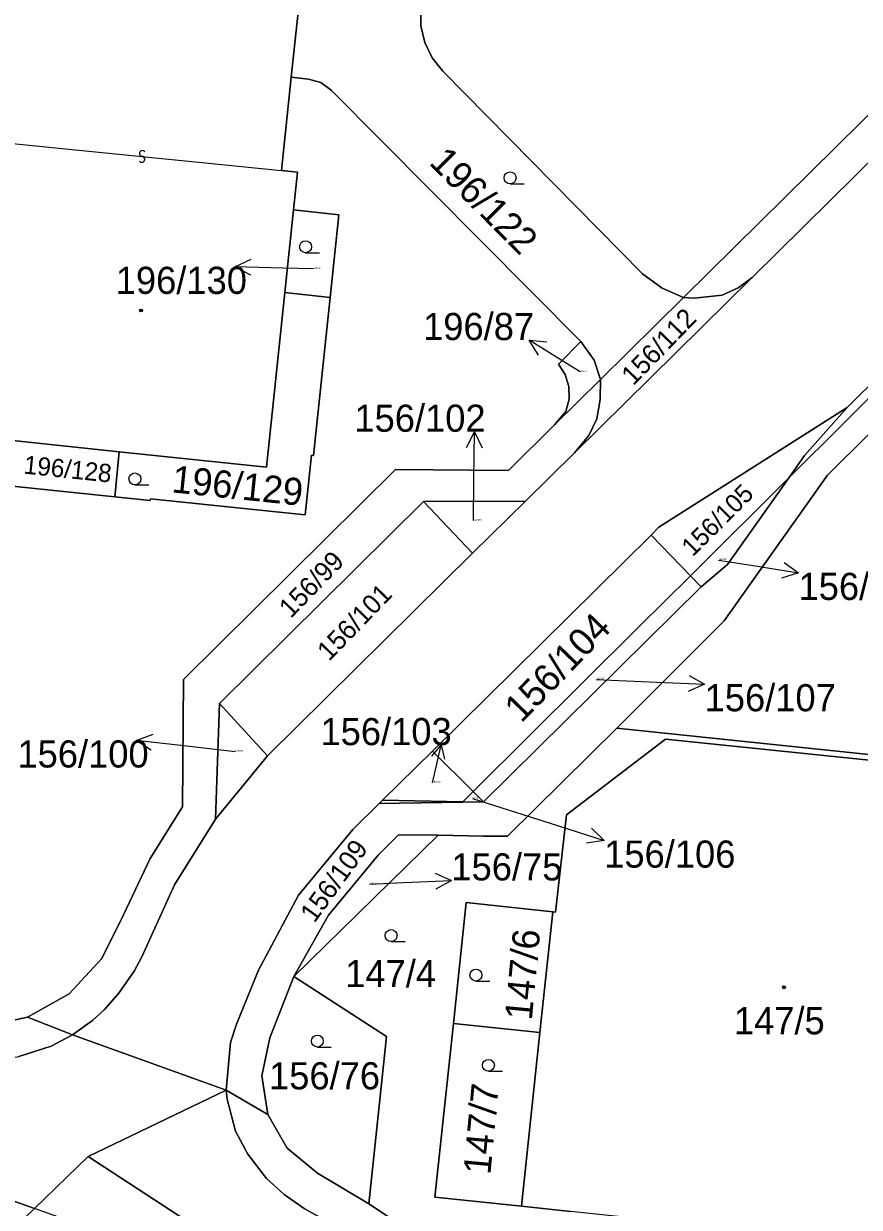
# Model space of a CAD drawing. Extents: x -598233 to -596890, y -1157848 to -1156431.
# Drawn here: x -597801.7 to -597749.4, y -1156820.9 to -1156746.8 of the extents above; entities that cross this region are included whole.
import ezdxf

# ---------------------------------------------------------------- set-up
doc = ezdxf.new("R2010")
doc.units = 0
for name, color, linetype in [('Level 1', 7, 'Continuous'), ('Level 13', 7, 'Continuous'), ('Level 3', 7, 'Continuous'), ('Level 4', 7, 'Continuous'), ('Level 5', 7, 'Continuous'), ('Level 57', 7, 'Continuous'), ('Level 60', 7, 'Continuous')]:
    doc.layers.add(name, color=color, linetype=linetype)

msp = doc.modelspace()

# ---------------------------------------------------------------- linework, layer by layer
at = {"layer": 'Level 1'}
for points in [[(-597750.17, -1156770.82), (-597735.18, -1156755.99), (-597734.6, -1156755.26), (-597730.11, -1156746.9), (-597683.93, -1156701.31), (-597681.14, -1156698.43), (-597679.19, -1156696.78), (-597678.75, -1156696.58)], [(-597760.41, -1156763.93), (-597733.37, -1156737.22), (-597732.06, -1156734.8), (-597732.17, -1156732.25)], [(-597731.89, -1156738.74), (-597756.11, -1156762.68)], [(-597784.23, -1156743.15), (-597784.97, -1156750.15)], [(-597776.66, -1156743.94), (-597776.86, -1156745.86), (-597776.85, -1156746.93), (-597776.61, -1156747.97), (-597776.15, -1156748.94), (-597775.48, -1156749.77), (-597762.97, -1156762.45), (-597761.74, -1156763.35), (-597760.41, -1156763.93)], [(-597784.97, -1156750.15), (-597785.58, -1156755.99)], [(-597766.84, -1156766.68), (-597782.48, -1156750.95), (-597783.13, -1156750.48), (-597783.9, -1156750.26), (-597784.97, -1156750.15)], [(-597731.29, -1156753.36), (-597733.27, -1156757.08), (-597751.4, -1156775.05), (-597757.86, -1156784.17), (-597764.59, -1156790.9)], [(-597753.8, -1156775.21), (-597746.94, -1156768.39), (-597731.29, -1156753.36)], [(-597785.58, -1156755.99), (-597784.59, -1156756.09), (-597784.84, -1156758.45)], [(-597784.84, -1156758.45), (-597785.38, -1156763.63)], [(-597782.54, -1156763.93), (-597782, -1156758.75), (-597784.84, -1156758.45)], [(-597767.23, -1156773.66), (-597756.11, -1156762.68)], [(-597756.11, -1156762.68), (-597756.95, -1156763.31), (-597758, -1156763.78), (-597759.75, -1156763.98), (-597760.41, -1156763.93)], [(-597785.38, -1156763.63), (-597786.52, -1156774.55), (-597795.74, -1156773.59)], [(-597785.38, -1156763.63), (-597782.54, -1156763.93)], [(-597782.54, -1156763.93), (-597783.58, -1156773.83), (-597783.71, -1156773.81), (-597784.1, -1156777.54), (-597793.79, -1156776.53), (-597793.8, -1156776.65), (-597796.03, -1156776.42)], [(-597760.41, -1156763.93), (-597765.61, -1156769.06)], [(-597766.84, -1156766.68), (-597768.25, -1156768.11), (-597767.82, -1156768.76), (-597767.59, -1156769.51), (-597767.57, -1156770.3), (-597767.79, -1156771.07), (-597768.48, -1156771.9)], [(-597766.84, -1156766.68), (-597766.01, -1156767.86), (-597765.61, -1156769.06)], [(-597765.61, -1156769.06), (-597768.48, -1156771.9)], [(-597767.23, -1156773.66), (-597766.35, -1156772.57), (-597765.84, -1156771.54), (-597765.63, -1156770.33), (-597765.61, -1156769.06)], [(-597762.44, -1156778.82), (-597761.95, -1156778.31), (-597750.17, -1156770.82)], [(-597750.17, -1156770.82), (-597752.83, -1156773.83), (-597753.8, -1156775.21)], [(-597768.48, -1156771.9), (-597771.37, -1156774.76), (-597778.44, -1156774.71), (-597791.73, -1156787.84), (-597791.78, -1156795.82), (-597793.81, -1156799.06), (-597795.48, -1156802.59), (-597796.83, -1156805.32), (-597798.87, -1156807.52), (-597801.48, -1156809)], [(-597796.03, -1156776.42), (-597805.27, -1156775.45), (-597804.98, -1156772.62)], [(-597795.74, -1156773.59), (-597804.98, -1156772.62)], [(-597796.03, -1156776.42), (-597795.74, -1156773.59)], [(-597770.31, -1156776.68), (-597767.23, -1156773.66)], [(-597759.98, -1156781.35), (-597753.8, -1156775.21)], [(-597759.3, -1156782.05), (-597757.66, -1156780.66), (-597753.8, -1156775.21)], [(-597789.46, -1156789.36), (-597776.69, -1156776.71)], [(-597776.69, -1156776.71), (-597770.31, -1156776.68)], [(-597776.69, -1156776.71), (-597773.63, -1156779.95)], [(-597770.31, -1156776.68), (-597773.63, -1156779.95)], [(-597776.13, -1156792.33), (-597762.44, -1156778.82)], [(-597759.98, -1156781.35), (-597762.44, -1156778.82)], [(-597773.63, -1156779.95), (-597786.47, -1156792.63)], [(-597773.59, -1156794.86), (-597763.24, -1156784.58), (-597759.98, -1156781.35)], [(-597759.3, -1156782.05), (-597759.98, -1156781.35)], [(-597759.3, -1156782.05), (-597772.94, -1156795.51)], [(-597789.46, -1156789.36), (-597789.71, -1156796.6)], [(-597786.47, -1156792.63), (-597789.46, -1156789.36)], [(-597775.77, -1156797.6), (-597772.94, -1156797.65), (-597771.43, -1156797.65), (-597764.59, -1156790.9)], [(-597764.59, -1156790.9), (-597745.4, -1156792.91)], [(-597768.59, -1156802.39), (-597768.42, -1156802.41), (-597767.74, -1156796.33), (-597761.55, -1156791.58), (-597737.44, -1156794.07), (-597740.62, -1156823.77), (-597742.4, -1156823.59)], [(-597789.71, -1156796.6), (-597786.47, -1156792.63)], [(-597779.26, -1156795.41), (-597776.13, -1156792.33)], [(-597776.13, -1156792.33), (-597773.59, -1156794.86)], [(-597773.59, -1156794.86), (-597774.24, -1156795.5), (-597779.26, -1156795.41)], [(-597773.59, -1156794.86), (-597772.94, -1156795.51)], [(-597779.47, -1156795.62), (-597781.12, -1156797.24), (-597784.51, -1156801.35), (-597787.02, -1156806.05), (-597788.4, -1156809.43), (-597788.78, -1156810.58), (-597789.04, -1156813.57)], [(-597779.47, -1156795.62), (-597779.26, -1156795.41)], [(-597772.94, -1156795.51), (-597779.47, -1156795.62)], [(-597798.68, -1156810.1), (-597797.42, -1156809.19), (-597796.67, -1156808.5), (-597795.77, -1156807.49), (-597794.82, -1156806.12), (-597794.33, -1156805.21), (-597792.28, -1156800.71), (-597789.71, -1156796.6)], [(-597775.77, -1156797.6), (-597778.26, -1156797.58), (-597779.54, -1156798.84), (-597782.64, -1156802.6), (-597784.82, -1156806.44)], [(-597775.77, -1156797.6), (-597784.82, -1156806.44)], [(-597768.59, -1156802.39), (-597774.02, -1156801.82), (-597774.82, -1156809.38)], [(-597769.4, -1156809.95), (-597768.59, -1156802.39)], [(-597801.48, -1156809), (-597804.42, -1156809.62), (-597807.4, -1156809.34), (-597812.36, -1156808.22), (-597817.37, -1156807.35), (-597822.41, -1156806.73), (-597827.48, -1156806.37), (-597836.01, -1156805.98), (-597837.54, -1156805.91), (-597839.05, -1156805.84), (-597839.64, -1156805.81)], [(-597784.82, -1156806.44), (-597786.32, -1156810.29), (-597786.82, -1156812.67), (-597786.44, -1156815.08)], [(-597784.82, -1156806.44), (-597779.01, -1156810.19), (-597780.11, -1156820.68)], [(-597836.2, -1156808.1), (-597829.16, -1156808.42), (-597825.15, -1156808.67), (-597817.18, -1156809.57), (-597812.21, -1156810.42), (-597807.35, -1156811.52), (-597806.36, -1156811.78), (-597805.14, -1156811.86), (-597803.99, -1156811.81), (-597802.03, -1156811.45), (-597800.01, -1156810.81), (-597798.68, -1156810.1)], [(-597798.68, -1156810.1), (-597801.48, -1156809)], [(-597774.82, -1156809.38), (-597775.98, -1156820.26), (-597770.56, -1156820.83)], [(-597774.82, -1156809.38), (-597769.4, -1156809.95)], [(-597789.04, -1156813.57), (-597798.68, -1156810.1)], [(-597769.4, -1156809.95), (-597770.56, -1156820.83)], [(-597789.04, -1156813.57), (-597797.68, -1156817.71)], [(-597758.96, -1156837.3), (-597779, -1156824.02), (-597781.84, -1156822.26), (-597784.16, -1156820.96), (-597785.42, -1156820.1), (-597786.53, -1156819.08), (-597787.7, -1156817.57), (-597788.47, -1156816.13), (-597788.99, -1156814.13), (-597789.04, -1156813.57)], [(-597786.44, -1156815.08), (-597789.04, -1156813.57)], [(-597786.44, -1156815.08), (-597785.23, -1156817.2), (-597783.34, -1156818.75), (-597780.11, -1156820.68)], [(-597801.05, -1156820.96), (-597805.48, -1156819.41), (-597808.5, -1156818.55), (-597813.36, -1156817.31)], [(-597797.68, -1156817.71), (-597801.05, -1156820.96)], [(-597797.68, -1156817.71), (-597707.2, -1156876.79)], [(-597756.23, -1156836.53), (-597780.11, -1156820.68)], [(-597770.56, -1156820.83), (-597767.49, -1156821.15)]]:
    msp.add_lwpolyline(points, dxfattribs=at)
at = {"layer": 'Level 13'}
for centre, start, end in [((-597794.29, -1156754.917), 31.58746, 263.68546), ((-597794.329, -1156755.283), 211.37301, 83.96301)]:
    msp.add_arc(centre, 0.184, start, end, dxfattribs=at)
at = {"layer": 'Level 3'}
msp.add_lwpolyline([(-597803.05, -1156754.22), (-597785.58, -1156755.99)], dxfattribs=at)
at = {"layer": 'Level 5'}
for p, q in [((-597771.27, -1156756.82), (-597770.395, -1156756.82)), ((-597784.08, -1156761.13), (-597783.205, -1156761.13)), ((-597794.76, -1156775.67), (-597793.885, -1156775.67)), ((-597778.72, -1156804.26), (-597777.845, -1156804.26)), ((-597773.41, -1156806.73), (-597772.535, -1156806.73)), ((-597783.34, -1156810.86), (-597782.465, -1156810.86)), ((-597772.63, -1156812.38), (-597771.755, -1156812.38))]:
    msp.add_line(p, q, dxfattribs=at)
for centre, radius in [((-597771.27, -1156756.445), 0.375), ((-597784.08, -1156760.755), 0.375), ((-597794.38, -1156764.75), 0.09), ((-597794.38, -1156764.75), 0.0521), ((-597794.76, -1156775.295), 0.375), ((-597778.72, -1156803.885), 0.375), ((-597773.41, -1156806.355), 0.375), ((-597754.12, -1156807.12), 0.09), ((-597754.12, -1156807.12), 0.0521), ((-597783.34, -1156810.485), 0.375), ((-597772.63, -1156812.005), 0.375)]:
    msp.add_circle(centre, radius, dxfattribs=at)
at = {"layer": 'Level 57'}
for p, q in [((-597785.501, -1156762.089), (-597788.5, -1156762.01)), ((-597783.59, -1156762.14), (-597785.501, -1156762.089)), ((-597767.536, -1156768.187), (-597770.082, -1156766.6)), ((-597766.89, -1156768.59), (-597767.536, -1156768.187)), ((-597773.532, -1156775.34), (-597773.499, -1156772.34)), ((-597773.56, -1156777.9), (-597773.532, -1156775.34)), ((-597758.22, -1156780.37), (-597756.172, -1156780.697)), ((-597756.172, -1156780.697), (-597753.21, -1156781.17)), ((-597765.89, -1156787.84), (-597762.087, -1156788.008)), ((-597762.087, -1156788.008), (-597759.09, -1156788.14)), ((-597791.699, -1156792.001), (-597794.68, -1156791.66)), ((-597788.48, -1156792.37), (-597791.699, -1156792.001)), ((-597776.12, -1156794.31), (-597775.597, -1156791.96)), ((-597773.62, -1156795.3), (-597768.238, -1156797.018)), ((-597768.238, -1156797.018), (-597765.38, -1156797.93)), ((-597780.08, -1156800.66), (-597777.945, -1156800.564)), ((-597777.945, -1156800.564), (-597774.948, -1156800.43))]:
    msp.add_line(p, q, dxfattribs=at)
for points in [[(-597787.514, -1156762.536), (-597788.5, -1156762.01), (-597787.487, -1156761.536)], [(-597769.498, -1156767.553), (-597770.082, -1156766.6), (-597768.969, -1156766.705)], [(-597774.01, -1156773.335), (-597773.499, -1156772.34), (-597773.01, -1156773.346)], [(-597754.118, -1156780.519), (-597753.21, -1156781.17), (-597754.276, -1156781.506)], [(-597760.067, -1156787.597), (-597759.09, -1156788.14), (-597760.111, -1156788.596)], [(-597793.743, -1156792.27), (-597794.68, -1156791.66), (-597793.629, -1156791.277)], [(-597776.163, -1156792.656), (-597775.597, -1156791.96), (-597775.379, -1156792.831)], [(-597766.181, -1156797.15), (-597765.38, -1156797.93), (-597766.485, -1156798.102)], [(-597775.969, -1156799.975), (-597774.948, -1156800.43), (-597775.925, -1156800.974)]]:
    msp.add_lwpolyline(points, dxfattribs=at)
at = {"layer": 'Level 60'}
for points in [[(-597752.83, -1156773.83), (-597750.17, -1156770.82), (-597735.18, -1156755.99), (-597734.6, -1156755.26), (-597730.11, -1156746.9), (-597683.93, -1156701.31), (-597681.14, -1156698.43), (-597679.19, -1156696.78), (-597678.75, -1156696.58), (-597675.04, -1156699.81), (-597675.83, -1156699.36), (-597676.94, -1156699.05), (-597678.16, -1156699.1), (-597679.43, -1156699.58), (-597680.62, -1156700.99), (-597705.61, -1156725.68), (-597717.97, -1156737.89), (-597718.07, -1156737.79), (-597728.48, -1156748.08), (-597731.29, -1156753.36), (-597746.94, -1156768.39), (-597753.8, -1156775.21)], [(-597756.11, -1156762.68), (-597756.95, -1156763.31), (-597758, -1156763.78), (-597759.75, -1156763.98), (-597760.41, -1156763.93), (-597733.37, -1156737.22), (-597732.06, -1156734.8), (-597732.17, -1156732.25), (-597730.57, -1156730.67), (-597729.92, -1156732.43), (-597729.82, -1156733.16), (-597730.03, -1156735.4), (-597730.68, -1156737.11), (-597731.89, -1156738.74)], [(-597785.58, -1156755.99), (-597784.59, -1156756.09), (-597784.84, -1156758.45), (-597785.38, -1156763.63), (-597786.52, -1156774.55), (-597795.74, -1156773.59), (-597804.98, -1156772.62), (-597803.83, -1156761.7), (-597803.05, -1156754.22), (-597805.88, -1156753.92), (-597811.48, -1156753.34), (-597815.37, -1156752.93), (-597824.55, -1156751.97), (-597833.78, -1156751.01), (-597832.65, -1156740.21), (-597832.09, -1156734.89), (-597831.85, -1156732.55), (-597813.46, -1156734.47), (-597783.65, -1156737.59), (-597784.23, -1156743.15), (-597784.97, -1156750.15)], [(-597776.66, -1156743.94), (-597776.86, -1156745.86), (-597776.85, -1156746.93), (-597776.61, -1156747.97), (-597776.15, -1156748.94), (-597775.48, -1156749.77), (-597762.97, -1156762.45), (-597761.74, -1156763.35), (-597760.41, -1156763.93), (-597765.61, -1156769.06), (-597766.01, -1156767.86), (-597766.84, -1156766.68), (-597782.48, -1156750.95), (-597783.13, -1156750.48), (-597783.9, -1156750.26), (-597784.97, -1156750.15), (-597784.23, -1156743.15)], [(-597782, -1156758.75), (-597782.54, -1156763.93), (-597785.38, -1156763.63), (-597784.84, -1156758.45)], [(-597767.23, -1156773.66), (-597766.35, -1156772.57), (-597765.84, -1156771.54), (-597765.63, -1156770.33), (-597765.61, -1156769.06), (-597760.41, -1156763.93), (-597759.75, -1156763.98), (-597758, -1156763.78), (-597756.95, -1156763.31), (-597756.11, -1156762.68)], [(-597782.54, -1156763.93), (-597783.58, -1156773.83), (-597783.71, -1156773.81), (-597784.1, -1156777.54), (-597793.79, -1156776.53), (-597793.8, -1156776.65), (-597796.03, -1156776.42), (-597795.74, -1156773.59), (-597786.52, -1156774.55), (-597785.38, -1156763.63)], [(-597768.25, -1156768.11), (-597766.84, -1156766.68), (-597766.01, -1156767.86), (-597765.61, -1156769.06), (-597768.48, -1156771.9), (-597767.79, -1156771.07), (-597767.57, -1156770.3), (-597767.59, -1156769.51), (-597767.82, -1156768.76)], [(-597798.68, -1156810.1), (-597801.48, -1156809), (-597798.87, -1156807.52), (-597796.83, -1156805.32), (-597795.48, -1156802.59), (-597793.81, -1156799.06), (-597791.78, -1156795.82), (-597791.73, -1156787.84), (-597778.44, -1156774.71), (-597771.37, -1156774.76), (-597768.48, -1156771.9), (-597765.61, -1156769.06), (-597765.63, -1156770.33), (-597765.84, -1156771.54), (-597766.35, -1156772.57), (-597767.23, -1156773.66), (-597770.31, -1156776.68), (-597776.69, -1156776.71), (-597789.46, -1156789.36), (-597789.71, -1156796.6), (-597792.28, -1156800.71), (-597794.33, -1156805.21), (-597794.82, -1156806.12), (-597795.77, -1156807.49), (-597796.67, -1156808.5), (-597797.42, -1156809.19)], [(-597762.44, -1156778.82), (-597761.95, -1156778.31), (-597750.17, -1156770.82), (-597752.83, -1156773.83), (-597753.8, -1156775.21), (-597759.98, -1156781.35)], [(-597796.03, -1156776.42), (-597805.27, -1156775.45), (-597804.98, -1156772.62), (-597795.74, -1156773.59)], [(-597757.66, -1156780.66), (-597759.3, -1156782.05), (-597759.98, -1156781.35), (-597753.8, -1156775.21)], [(-597786.47, -1156792.63), (-597789.46, -1156789.36), (-597776.69, -1156776.71), (-597773.63, -1156779.95)], [(-597773.63, -1156779.95), (-597776.69, -1156776.71), (-597770.31, -1156776.68)], [(-597776.13, -1156792.33), (-597762.44, -1156778.82), (-597759.98, -1156781.35), (-597763.24, -1156784.58), (-597773.59, -1156794.86)], [(-597759.3, -1156782.05), (-597772.94, -1156795.51), (-597773.59, -1156794.86), (-597763.24, -1156784.58), (-597759.98, -1156781.35)], [(-597786.47, -1156792.63), (-597789.71, -1156796.6), (-597789.46, -1156789.36)], [(-597768.59, -1156802.39), (-597768.42, -1156802.41), (-597767.74, -1156796.33), (-597761.55, -1156791.58), (-597737.44, -1156794.07), (-597740.62, -1156823.77), (-597742.4, -1156823.59), (-597752.08, -1156822.59), (-597752.1, -1156822.76), (-597762.12, -1156821.71), (-597767.49, -1156821.15), (-597770.56, -1156820.83), (-597769.4, -1156809.95)], [(-597779.26, -1156795.41), (-597776.13, -1156792.33), (-597773.59, -1156794.86), (-597774.24, -1156795.5)], [(-597772.94, -1156795.51), (-597779.47, -1156795.62), (-597779.26, -1156795.41), (-597774.24, -1156795.5), (-597773.59, -1156794.86)], [(-597775.77, -1156797.6), (-597784.82, -1156806.44), (-597782.64, -1156802.6), (-597779.54, -1156798.84), (-597778.26, -1156797.58)], [(-597774.02, -1156801.82), (-597768.59, -1156802.39), (-597769.4, -1156809.95), (-597774.82, -1156809.38)], [(-597784.82, -1156806.44), (-597779.01, -1156810.19), (-597780.11, -1156820.68), (-597783.34, -1156818.75), (-597785.23, -1156817.2), (-597786.44, -1156815.08), (-597786.82, -1156812.67), (-597786.32, -1156810.29)], [(-597775.98, -1156820.26), (-597774.82, -1156809.38), (-597769.4, -1156809.95), (-597770.56, -1156820.83)], [(-597758.96, -1156837.3), (-597749.3, -1156843.75), (-597736.98, -1156851.89), (-597712.09, -1156868.35), (-597711.15, -1156868.78), (-597704.79, -1156872.9), (-597707.2, -1156876.79), (-597797.68, -1156817.71), (-597789.04, -1156813.57), (-597788.99, -1156814.13), (-597788.47, -1156816.13), (-597787.7, -1156817.57), (-597786.53, -1156819.08), (-597785.42, -1156820.1), (-597784.16, -1156820.96), (-597781.84, -1156822.26), (-597779, -1156824.02)], [(-597757.99, -1156837.72), (-597758.96, -1156837.3), (-597779, -1156824.02), (-597781.84, -1156822.26), (-597784.16, -1156820.96), (-597785.42, -1156820.1), (-597786.53, -1156819.08), (-597787.7, -1156817.57), (-597788.47, -1156816.13), (-597788.99, -1156814.13), (-597789.04, -1156813.57), (-597786.44, -1156815.08), (-597785.23, -1156817.2), (-597783.34, -1156818.75), (-597780.11, -1156820.68), (-597756.23, -1156836.53), (-597755.31, -1156837.14), (-597756.13, -1156837.6), (-597757.12, -1156837.85)], [(-597805.48, -1156819.41), (-597801.05, -1156820.96), (-597802.67, -1156822.53), (-597806.11, -1156821.35), (-597808.93, -1156820.54), (-597811.11, -1156819.98), (-597811.91, -1156819.86), (-597812.39, -1156819.89), (-597812.98, -1156820.06), (-597813.31, -1156820.38), (-597813.5, -1156820.93), (-597813.53, -1156821.4), (-597816.66, -1156820.88), (-597813.36, -1156817.31), (-597808.5, -1156818.55)], [(-597794.07, -1156823.89), (-597799.58, -1156821.48), (-597801.05, -1156820.96), (-597797.68, -1156817.71), (-597707.2, -1156876.79), (-597708.61, -1156879.07), (-597719.09, -1156872.12), (-597720.31, -1156871.32), (-597740.07, -1156858.27), (-597740.76, -1156857.8), (-597741.3, -1156857.46), (-597760.9, -1156844.44), (-597762.14, -1156843.6), (-597782.73, -1156829.95), (-597788.59, -1156826.54)]]:
    msp.add_lwpolyline(points, close=True, dxfattribs=at)
for points in [[(-597691.18, -1156778.7), (-597720.91, -1156775.59), (-597739.41, -1156773.66), (-597739.65, -1156775.95), (-597743.58, -1156775.54), (-597744.14, -1156780.92), (-597745.4, -1156792.91), (-597764.59, -1156790.9), (-597757.86, -1156784.17), (-597751.4, -1156775.05), (-597733.27, -1156757.08), (-597731.29, -1156753.36), (-597716.61, -1156739.26), (-597717.97, -1156737.89), (-597705.61, -1156725.68)], [(-597733.37, -1156737.22), (-597760.41, -1156763.93), (-597761.74, -1156763.35), (-597762.97, -1156762.45), (-597775.48, -1156749.77), (-597776.15, -1156748.94), (-597776.61, -1156747.97), (-597776.85, -1156746.93), (-597776.86, -1156745.86)], [(-597735.18, -1156755.99), (-597750.17, -1156770.82), (-597761.95, -1156778.31), (-597762.44, -1156778.82), (-597776.13, -1156792.33), (-597779.26, -1156795.41), (-597779.47, -1156795.62), (-597781.12, -1156797.24), (-597784.51, -1156801.35), (-597787.02, -1156806.05), (-597788.4, -1156809.43), (-597788.78, -1156810.58), (-597789.04, -1156813.57), (-597798.68, -1156810.1), (-597797.42, -1156809.19), (-597796.67, -1156808.5), (-597795.77, -1156807.49), (-597794.82, -1156806.12), (-597794.33, -1156805.21), (-597792.28, -1156800.71), (-597789.71, -1156796.6), (-597786.47, -1156792.63), (-597773.63, -1156779.95), (-597770.31, -1156776.68), (-597767.23, -1156773.66), (-597756.11, -1156762.68), (-597731.89, -1156738.74)], [(-597805.27, -1156775.45), (-597796.03, -1156776.42), (-597793.8, -1156776.65), (-597793.79, -1156776.53), (-597784.1, -1156777.54), (-597783.71, -1156773.81), (-597783.58, -1156773.83), (-597782.54, -1156763.93), (-597782, -1156758.75), (-597784.84, -1156758.45), (-597784.59, -1156756.09), (-597785.58, -1156755.99), (-597784.97, -1156750.15), (-597783.9, -1156750.26), (-597783.13, -1156750.48), (-597782.48, -1156750.95), (-597766.84, -1156766.68), (-597768.25, -1156768.11), (-597767.82, -1156768.76), (-597767.59, -1156769.51), (-597767.57, -1156770.3), (-597767.79, -1156771.07), (-597768.48, -1156771.9), (-597771.37, -1156774.76), (-597778.44, -1156774.71)], [(-597733.27, -1156757.08), (-597751.4, -1156775.05), (-597757.86, -1156784.17), (-597764.59, -1156790.9), (-597771.43, -1156797.65), (-597772.94, -1156797.65), (-597775.77, -1156797.6), (-597778.26, -1156797.58), (-597779.54, -1156798.84), (-597782.64, -1156802.6), (-597784.82, -1156806.44), (-597786.32, -1156810.29), (-597786.82, -1156812.67), (-597786.44, -1156815.08), (-597789.04, -1156813.57), (-597788.78, -1156810.58), (-597788.4, -1156809.43), (-597787.02, -1156806.05), (-597784.51, -1156801.35), (-597781.12, -1156797.24), (-597779.47, -1156795.62), (-597772.94, -1156795.51), (-597759.3, -1156782.05), (-597757.66, -1156780.66), (-597753.8, -1156775.21), (-597746.94, -1156768.39)], [(-597778.44, -1156774.71), (-597791.73, -1156787.84), (-597791.78, -1156795.82), (-597793.81, -1156799.06), (-597795.48, -1156802.59), (-597796.83, -1156805.32), (-597798.87, -1156807.52), (-597801.48, -1156809), (-597804.42, -1156809.62)], [(-597756.23, -1156836.53), (-597780.11, -1156820.68), (-597779.01, -1156810.19), (-597784.82, -1156806.44), (-597775.77, -1156797.6), (-597772.94, -1156797.65), (-597771.43, -1156797.65), (-597764.59, -1156790.9), (-597745.4, -1156792.91), (-597737.13, -1156793.77), (-597737.42, -1156796.53), (-597740.29, -1156823.96)], [(-597740.62, -1156823.77), (-597737.44, -1156794.07), (-597761.55, -1156791.58), (-597767.74, -1156796.33), (-597768.42, -1156802.41), (-597768.59, -1156802.39), (-597774.02, -1156801.82), (-597774.82, -1156809.38), (-597775.98, -1156820.26), (-597770.56, -1156820.83), (-597767.49, -1156821.15)], [(-597804.42, -1156809.62), (-597801.48, -1156809), (-597798.68, -1156810.1), (-597800.01, -1156810.81), (-597802.03, -1156811.45)], [(-597802.03, -1156811.45), (-597800.01, -1156810.81), (-597798.68, -1156810.1), (-597789.04, -1156813.57), (-597797.68, -1156817.71), (-597801.05, -1156820.96), (-597805.48, -1156819.41)]]:
    msp.add_lwpolyline(points, dxfattribs=at)

# ---------------------------------------------------------------- texts
at = {"layer": 'Level 4'}
for s, height, rotation, p in [('196/122', 1.7, 314.83566, (-597776.402, -1156755.543)), ('156/112', 1.2, 45.9, (-597763.557, -1156769.501)), ('196/128', 1.14, 354.0429, (-597801.763, -1156774.953)), ('196/129', 1.7, 354.0429, (-597792.506, -1156776.126)), ('156/105', 1.14, 44.87238, (-597759.846, -1156780.208)), ('156/99', 1.2, 45.9, (-597784.998, -1156784.061)), ('156/101', 1.2, 45.9, (-597782.607, -1156786.75)), ('156/104', 1.7, 45.9, (-597770.562, -1156790.615)), ('156/109', 1.2, 54, (-597783.525, -1156803.143)), ('147/6', 1.7, 84.6, (-597769.913, -1156809.225)), ('147/7', 1.7, 84.6, (-597772.509, -1156818.889))]:
    msp.add_text(s, height=height, rotation=rotation, dxfattribs=at).set_placement(p)
for s, height, p in [('196/130', 0.1, (-597783.59, -1156762.14)), ('196/87', 0.1, (-597766.89, -1156768.59)), ('156/102', 0.1, (-597773.56, -1156777.9)), ('156/108', 0.1, (-597758.22, -1156780.37)), ('156/107', 0.1, (-597765.89, -1156787.84)), ('156/100', 0.1, (-597788.48, -1156792.37)), ('156/103', 0.1, (-597776.12, -1156794.31)), ('156/106', 0.1, (-597773.62, -1156795.3)), ('156/75', 0.1, (-597780.08, -1156800.66)), ('147/4', 1.7, (-597781.597, -1156807.11)), ('147/5', 1.7, (-597757.258, -1156810.06)), ('156/76', 1.7, (-597786.366, -1156813.51))]:
    msp.add_text(s, height=height, dxfattribs=at).set_placement(p)
at = {"layer": 'Level 57'}
for s, p in [('196/130', (-597795.964, -1156763.71)), ('196/87', (-597776.719, -1156766.6)), ('156/102', (-597781.021, -1156772.34)), ('156/108', (-597753.21, -1156782.87)), ('156/107', (-597759.09, -1156789.84)), ('156/103', (-597783.143, -1156791.96)), ('156/100', (-597802.12, -1156793.36)), ('156/106', (-597765.38, -1156799.63)), ('156/75', (-597774.948, -1156800.43))]:
    msp.add_text(s, height=1.7, dxfattribs=at).set_placement(p)

doc.saveas('drawing.dxf')
